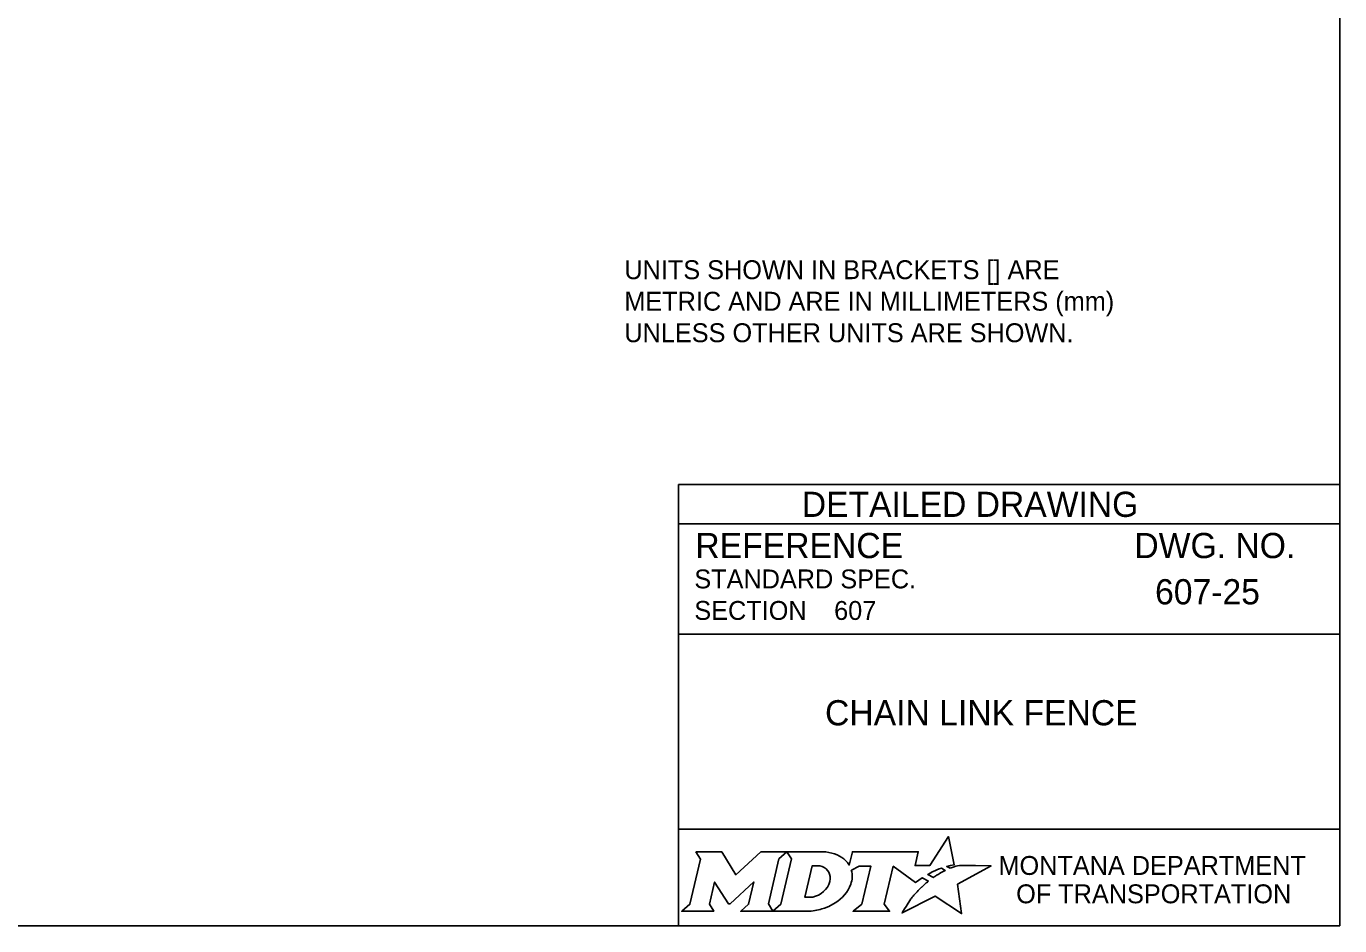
# Model space of a CAD drawing. Extents: x 49973.1 to 50021, y 49987.6 to 50015.4.
# Drawn here: x 50012.579 to 50016.75, y 49987.799 to 49990.653 of the extents above; entities that cross this region are included whole.
import ezdxf

# ---------------------------------------------------------------- set-up
doc = ezdxf.new("R2010")
doc.units = 0
for name, color, linetype in [('Default', 7, 'Continuous'), ('Level 1', 7, 'Continuous'), ('Level 2', 7, 'Continuous'), ('Level 5', 7, 'Continuous')]:
    doc.layers.add(name, color=color, linetype=linetype)

msp = doc.modelspace()

# ---------------------------------------------------------------- linework, layer by layer
at = {"layer": 'Default'}
for points in [[(50015.5126, 49987.9811), (50015.5023, 49987.9867), (50015.5139, 49987.9895), (50015.5255, 49987.9915), (50015.5081, 49988.0816), (50015.4486, 49987.9903), (50015.4013, 49987.9896), (50015.4116, 49988.0337), (50015.2024, 49988.0338), (50015.1923, 49987.9913), (50015.1865, 49987.9996)], [(50014.7056, 49988.0338), (50014.7197, 49988.0104), (50014.6862, 49987.8671), (50014.6605, 49987.8446), (50014.7621, 49987.8446), (50014.7486, 49987.8674), (50014.7648, 49987.9375), (50014.8085, 49987.8685), (50014.8138, 49987.8685), (50014.8889, 49987.938), (50014.8725, 49987.8669), (50014.8478, 49987.8449), (50014.9494, 49987.8449), (50014.9356, 49987.8682), (50014.9688, 49988.0106)], [(50014.9688, 49988.0106), (50014.9941, 49988.0338), (50014.9117, 49988.0338), (50014.8321, 49987.9608), (50014.7876, 49988.0335), (50014.7056, 49988.0338)], [(50015.1077, 49988.0338), (50014.9941, 49988.0338), (50015.0088, 49988.0109), (50014.9749, 49987.8671), (50014.9494, 49987.8449), (50015.06, 49987.8449)], [(50015.1317, 49987.9471), (50015.1305, 49987.939), (50015.1273, 49987.9297), (50015.1231, 49987.9215), (50015.1175, 49987.914), (50015.111, 49987.9071), (50015.1031, 49987.9008), (50015.0948, 49987.8961), (50015.0857, 49987.8922), (50015.0766, 49987.8899), (50015.0674, 49987.889), (50015.0515, 49987.889), (50015.0751, 49987.989), (50015.0911, 49987.989), (50015.0987, 49987.9884), (50015.1063, 49987.9865), (50015.1129, 49987.9835), (50015.119, 49987.9793), (50015.1238, 49987.9743), (50015.1275, 49987.9683), (50015.1302, 49987.9621), (50015.1318, 49987.9547), (50015.1318, 49987.9517), (50015.1317, 49987.9471)], [(50015.1991, 49987.9747), (50015.2237, 49987.9878), (50015.2606, 49987.9878), (50015.232, 49987.8673), (50015.2045, 49987.8446), (50015.3207, 49987.8446), (50015.3037, 49987.8675), (50015.3319, 49987.9877), (50015.4032, 49987.936), (50015.4243, 49987.9511), (50015.444, 49987.9402)], [(50015.3882, 49987.8843), (50015.3729, 49987.8599), (50015.3682, 49987.8524), (50015.3624, 49987.8438), (50015.3601, 49987.8395), (50015.4654, 49987.8926), (50015.5493, 49987.8375), (50015.5362, 49987.9302), (50015.6431, 49987.9886), (50015.5938, 49987.9894), (50015.5637, 49987.9898), (50015.5429, 49987.9901), (50015.5361, 49987.9886), (50015.5312, 49987.9874), (50015.5228, 49987.9851), (50015.5126, 49987.9811)], [(50015.4622, 49987.9535), (50015.4598, 49987.9518), (50015.4415, 49987.9614), (50015.4518, 49987.9671), (50015.4559, 49987.9693), (50015.4645, 49987.9733), (50015.4702, 49987.9759), (50015.4781, 49987.9789), (50015.4854, 49987.9816), (50015.4972, 49987.9742), (50015.4932, 49987.9721), (50015.4886, 49987.9696), (50015.4844, 49987.9674), (50015.4794, 49987.9645), (50015.4775, 49987.9634), (50015.4748, 49987.9618), (50015.4723, 49987.9604), (50015.47, 49987.9588), (50015.4674, 49987.957), (50015.4647, 49987.9552), (50015.4622, 49987.9535)], [(50015.4021, 49987.9004), (50015.4021, 49987.9004)], [(50015.1057, 49987.8522), (50015.1141, 49987.8548), (50015.1271, 49987.8602), (50015.1475, 49987.8712)]]:
    msp.add_lwpolyline(points, dxfattribs=at)
for centre, radius, start, end in [((50015.1308, 49987.9554), 0.0709, 339.5329, 15.8582), ((50015.0868, 49987.9727), 0.1183, 300.9103, 339.1383)]:
    msp.add_arc(centre, radius, start, end, dxfattribs=at)
for centre, major_axis, ratio, start_param, end_param in [((50015.1056, 49987.9864), (0.0834, -0.0037), 0.568097, 0.61298, 1.570796), ((50015.1612, 49987.9937), (0.0361, -0.0295), 0.469099, 1.225588, 1.570796), ((50015.4329, 49987.9305), (-0.0112, -0.0097), 0.021651, 3.157348, 6.283185), ((50015.3952, 49987.8923), (-0.00694, -0.00806), 0.008222, 0, 3.137361), ((50015.4119, 49987.9106), (-0.0098, -0.0102), 0.016458, 3.141593, 6.279097), ((50015.0603, 49987.9932), (0, 0.1484), 0.987302, 3.139398, 3.456847)]:
    msp.add_ellipse(centre, major_axis=major_axis, ratio=ratio, start_param=start_param, end_param=end_param, dxfattribs=at)
at = {"layer": 'Level 1'}
msp.add_lwpolyline([(49999.3835, 49998.9992), (50016.7501, 49998.9992), (50016.7501, 49987.7988), (49999.3835, 49987.7988)], close=True, dxfattribs=at)
at = {"layer": 'Level 5'}
for p, q in [((50016.7501, 49989.1988), (50014.6501, 49989.1988)), ((50014.6501, 49989.1988), (50014.6501, 49987.7988)), ((50016.7501, 49989.0738), (50014.6501, 49989.0738)), ((50016.3862, 49988.8587), (50016.3862, 49988.8587)), ((50015.1444, 49988.7993), (50015.1444, 49988.7993)), ((50016.7501, 49988.7238), (50014.6501, 49988.7238)), ((50015.7001, 49988.4747), (50015.7001, 49988.4747)), ((50016.7501, 49988.1057), (50014.6501, 49988.1057))]:
    msp.add_line(p, q, dxfattribs=at)

# ---------------------------------------------------------------- texts
at = {"layer": 'Default'}
for s, p in [('MONTANA DEPARTMENT', (50015.6663, 49987.96)), ('OF TRANSPORTATION', (50015.7225, 49987.87))]:
    msp.add_text(s, height=0.06, dxfattribs=at).set_placement(p)
at = {"layer": 'Level 2'}
for s, height, p in [('UNITS SHOWN IN BRACKETS [] ARE ', 0.06, (50014.4782, 49989.8508)), ('METRIC AND ARE IN MILLIMETERS (mm) ', 0.06, (50014.4782, 49989.7508)), ('UNLESS OTHER UNITS ARE SHOWN.', 0.06, (50014.4782, 49989.6508)), ('607-25', 0.08, (50016.1636, 49988.8187)), ('607', 0.06, (50015.1444, 49988.7693)), ('CHAIN LINK FENCE', 0.08, (50015.1155, 49988.4347))]:
    msp.add_text(s, height=height, dxfattribs=at).set_placement(p)
at = {"layer": 'Level 5'}
for s, height, p in [('DETAILED DRAWING', 0.0799, (50015.0418, 49989.0963)), ('REFERENCE', 0.08, (50014.7037, 49988.9654)), ('DWG. NO.', 0.08, (50016.0979, 49988.9654)), ('STANDARD SPEC.', 0.06, (50014.7004, 49988.8694)), ('SECTION', 0.06, (50014.7004, 49988.7694))]:
    msp.add_text(s, height=height, dxfattribs=at).set_placement(p)

doc.saveas('drawing.dxf')
